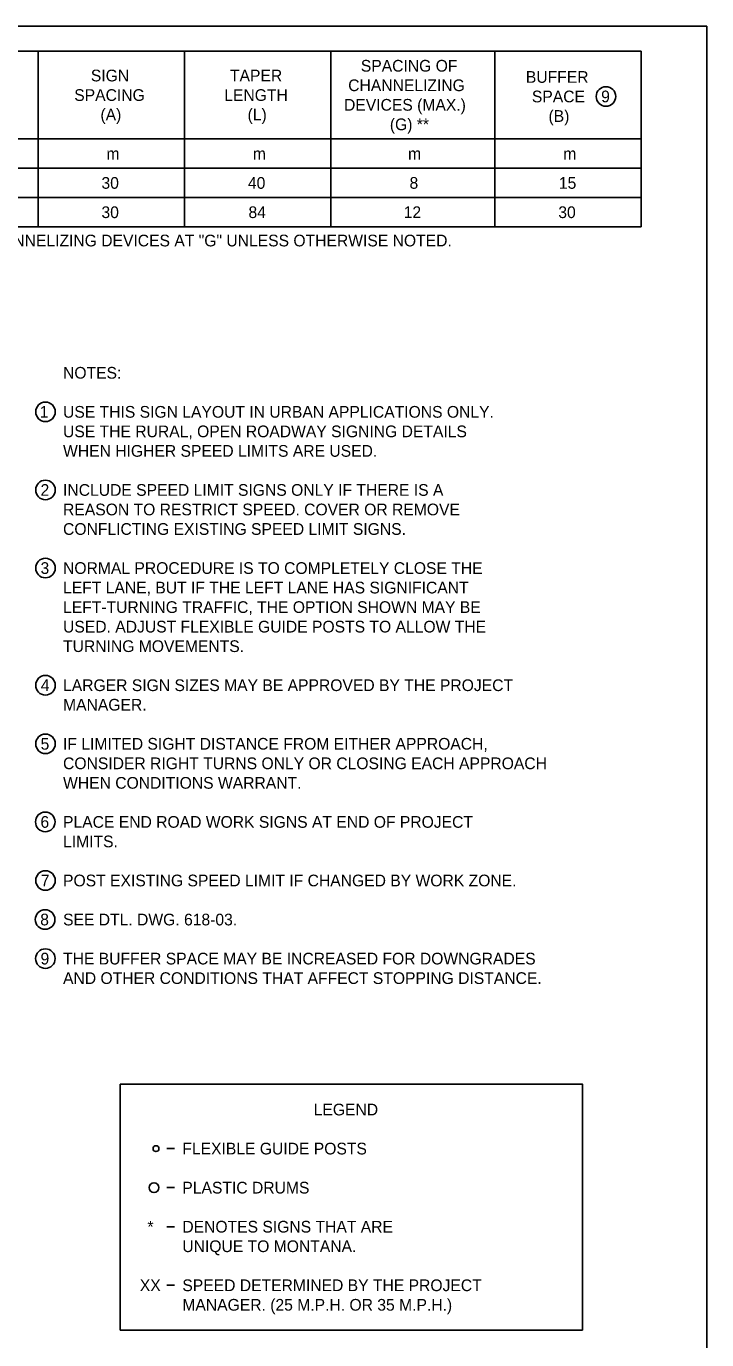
# Model space of a CAD drawing. Extents: x 49991.4 to 50021, y 49987.6 to 50011.4.
# Drawn here: x 50013.26 to 50016.75, y 49992.27 to 49999 of the extents above; entities that cross this region are included whole.
import ezdxf

# ---------------------------------------------------------------- set-up
doc = ezdxf.new("R2010")
doc.units = 0
doc.layers.add('Level 1', color=7, linetype='Continuous')
doc.layers.add('Level 2', color=7, linetype='Continuous')

msp = doc.modelspace()

# ---------------------------------------------------------------- linework, layer by layer
at = {"layer": 'Level 1'}
msp.add_lwpolyline([(49999.3835, 49998.9992), (50016.7501, 49998.9992), (50016.7501, 49987.7988), (49999.3835, 49987.7988)], close=True, dxfattribs=at)
for centre, radius in [((50013.929, 49993.2516), 0.015), ((50013.919, 49993.0516), 0.025)]:
    msp.add_circle(centre, radius, dxfattribs=at)
for start, end in [(360, 180), (180, 0)]:
    msp.add_arc((50013.919, 49993.0516), 0.025, start, end, dxfattribs=at)
at = {"layer": 'Level 2'}
for p, q in [((50012.4848, 49998.8719), (50016.4148, 49998.8719)), ((50013.3248, 49998.8719), (50013.3248, 49997.9719)), ((50014.0748, 49998.8719), (50014.0748, 49997.9719)), ((50014.8248, 49998.8719), (50014.8248, 49997.9719)), ((50015.6648, 49998.8719), (50015.6648, 49997.9719)), ((50016.4148, 49998.8719), (50016.4148, 49997.9719)), ((50012.4848, 49998.4219), (50016.4148, 49998.4219)), ((50012.4848, 49998.2719), (50016.4148, 49998.2719)), ((50012.4848, 49998.1219), (50016.4148, 49998.1219)), ((50012.4848, 49997.9719), (50016.4148, 49997.9719)), ((50013.7462, 49992.3216), (50013.7462, 49993.5816)), ((50014.024, 49993.2516), (50013.984, 49993.2516)), ((50013.984, 49993.0516), (50014.024, 49993.0516)), ((50014.024, 49992.8516), (50013.984, 49992.8516)), ((50014.024, 49992.5516), (50013.984, 49992.5516)), ((50016.1129, 49992.3216), (50013.7462, 49992.3216))]:
    msp.add_line(p, q, dxfattribs=at)
msp.add_lwpolyline([(50013.7462, 49993.5816), (50016.1129, 49993.5816), (50016.1129, 49992.3216)], dxfattribs=at)
for centre in [(50016.2339, 49998.6397), (50013.3629, 49997.0246), (50013.3629, 49996.6246), (50013.3629, 49996.2246), (50013.3629, 49995.6246), (50013.3629, 49995.3246), (50013.3618, 49994.9246), (50013.3629, 49994.6246), (50013.361, 49994.4246), (50013.3624, 49994.2246)]:
    msp.add_circle(centre, 0.0501, dxfattribs=at)

# ---------------------------------------------------------------- texts
for s, height, p in [('SPACING OF', 0.06, (50014.9783, 49998.7669)), ('SIGN', 0.06, (50013.5954, 49998.7169)), ('TAPER', 0.06, (50014.3081, 49998.7169)), ('BUFFER', 0.06, (50015.8237, 49998.7096)), ('SPACING', 0.06, (50013.5104, 49998.6169)), ('LENGTH', 0.06, (50014.2789, 49998.6169)), ('CHANNELIZING', 0.06, (50014.9136, 49998.6669)), ('SPACE', 0.06, (50015.8545, 49998.6096)), ('9', 0.06, (50016.2093, 49998.6097)), ('DEVICES (MAX.)', 0.06, (50014.8922, 49998.5669)), ('(A)', 0.06, (50013.6445, 49998.5169)), ('(L)', 0.06, (50014.3982, 49998.5169)), ('(B)', 0.06, (50015.9397, 49998.5096)), ('(G) **', 0.06, (50015.1269, 49998.4669)), ('m', 0.06, (50013.6752, 49998.3169)), ('m', 0.06, (50014.4252, 49998.3169)), ('m', 0.06, (50015.2202, 49998.3169)), ('m', 0.06, (50016.0152, 49998.3169)), ('30', 0.06, (50013.6498, 49998.1669)), ('40', 0.06, (50014.3998, 49998.1669)), ('8', 0.06, (50015.2278, 49998.1669)), ('15', 0.06, (50015.9928, 49998.1669)), ('30', 0.06, (50013.6498, 49998.0169)), ('84', 0.06, (50014.4028, 49998.0169)), ('12', 0.06, (50015.1978, 49998.0169)), ('30', 0.06, (50015.9898, 49998.0169)), ('** SPACE ALL CHANNELIZING DEVICES AT "G" UNLESS OTHERWISE NOTED.', 0.06, (50012.4848, 49997.8719)), ('NOTES:', 0.06, (50013.453, 49997.1946)), ('1', 0.06, (50013.3337, 49996.9947)), ('USE THIS SIGN LAYOUT IN URBAN APPLICATIONS ONLY.', 0.06, (50013.453, 49996.9946)), ('USE THE RURAL, OPEN ROADWAY SIGNING DETAILS', 0.06, (50013.453, 49996.8946)), ('WHEN HIGHER SPEED LIMITS ARE USED.', 0.06, (50013.453, 49996.7946)), ('2', 0.06, (50013.3378, 49996.5946)), ('INCLUDE SPEED LIMIT SIGNS ONLY IF THERE IS A', 0.06, (50013.453, 49996.5946)), ('REASON TO RESTRICT SPEED. COVER OR REMOVE', 0.06, (50013.453, 49996.4946)), ('CONFLICTING EXISTING SPEED LIMIT SIGNS.', 0.06, (50013.453, 49996.3946)), ('3', 0.06, (50013.3377, 49996.1946)), ('NORMAL PROCEDURE IS TO COMPLETELY CLOSE THE', 0.06, (50013.453, 49996.1946)), ('LEFT LANE, BUT IF THE LEFT LANE HAS SIGNIFICANT ', 0.06, (50013.453, 49996.0946)), ('LEFT-TURNING TRAFFIC, THE OPTION SHOWN MAY BE', 0.06, (50013.453, 49995.9946)), ('USED. ADJUST FLEXIBLE GUIDE POSTS TO ALLOW THE ', 0.06, (50013.453, 49995.8946)), ('TURNING MOVEMENTS.', 0.06, (50013.453, 49995.7946)), ('4', 0.06, (50013.3389, 49995.5946)), ('LARGER SIGN SIZES MAY BE APPROVED BY THE PROJECT', 0.06, (50013.453, 49995.5946)), ('MANAGER.', 0.06, (50013.453, 49995.4946)), ('5', 0.06, (50013.338, 49995.2946)), ('IF LIMITED SIGHT DISTANCE FROM EITHER APPROACH,', 0.06, (50013.453, 49995.2946)), ('CONSIDER RIGHT TURNS ONLY OR CLOSING EACH APPROACH', 0.06, (50013.453, 49995.1946)), ('WHEN CONDITIONS WARRANT.', 0.06, (50013.453, 49995.0946)), ('6', 0.06, (50013.3373, 49994.8946)), ('PLACE END ROAD WORK SIGNS AT END OF PROJECT', 0.06, (50013.453, 49994.8946)), ('LIMITS.', 0.06, (50013.453, 49994.7946)), ('7', 0.06, (50013.3391, 49994.5946)), ('POST EXISTING SPEED LIMIT IF CHANGED BY WORK ZONE.', 0.06, (50013.453, 49994.5946)), ('8', 0.06, (50013.336, 49994.3946)), ('SEE DTL. DWG. 618-03.', 0.06, (50013.453, 49994.3946)), ('9', 0.06, (50013.3378, 49994.1946)), ('THE BUFFER SPACE MAY BE INCREASED FOR DOWNGRADES ', 0.06, (50013.453, 49994.1946)), ('AND OTHER CONDITIONS THAT AFFECT STOPPING DISTANCE. ', 0.06, (50013.453, 49994.0946)), ('LEGEND', 0.06, (50014.7368, 49993.4216)), ('FLEXIBLE GUIDE POSTS', 0.06, (50014.064, 49993.2216)), ('PLASTIC DRUMS', 0.06, (50014.064, 49993.0216)), ('*', 0.0601, (50013.8853, 49992.8215)), ('DENOTES SIGNS THAT ARE', 0.06, (50014.064, 49992.8216)), ('UNIQUE TO MONTANA.', 0.06, (50014.064, 49992.7216)), ('XX', 0.06, (50013.8462, 49992.5216)), ('SPEED DETERMINED BY THE PROJECT', 0.06, (50014.064, 49992.5216)), ('MANAGER. (25 M.P.H. OR 35 M.P.H.)', 0.06, (50014.064, 49992.4216))]:
    msp.add_text(s, height=height, dxfattribs=at).set_placement(p)

doc.saveas('drawing.dxf')
